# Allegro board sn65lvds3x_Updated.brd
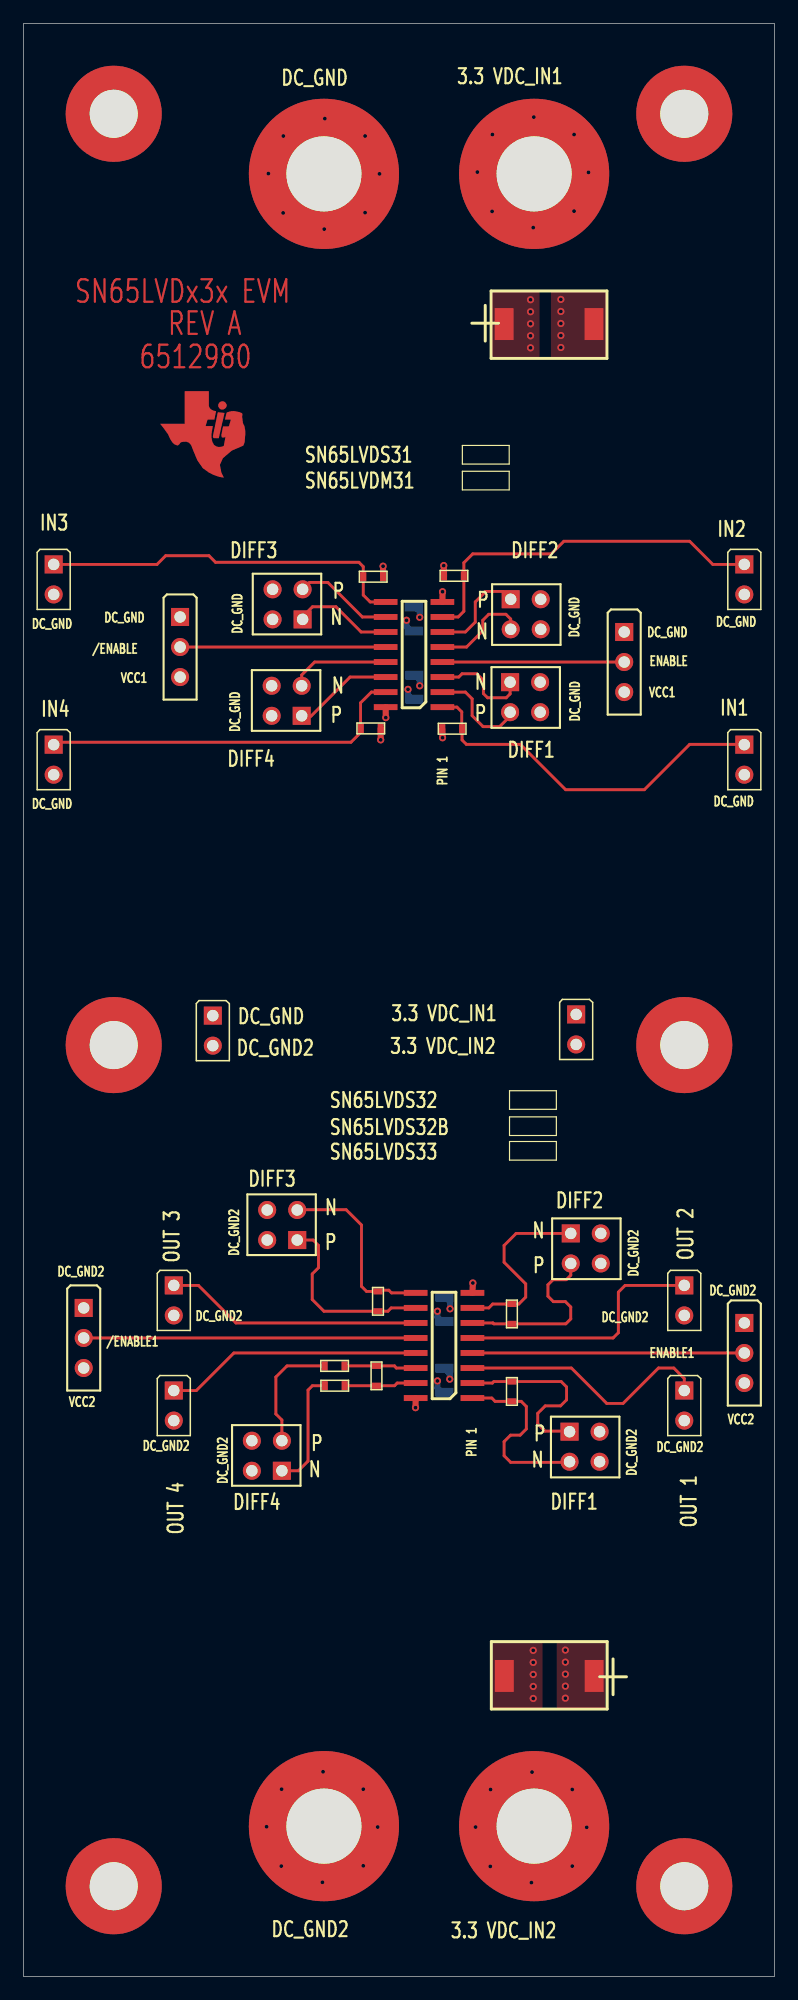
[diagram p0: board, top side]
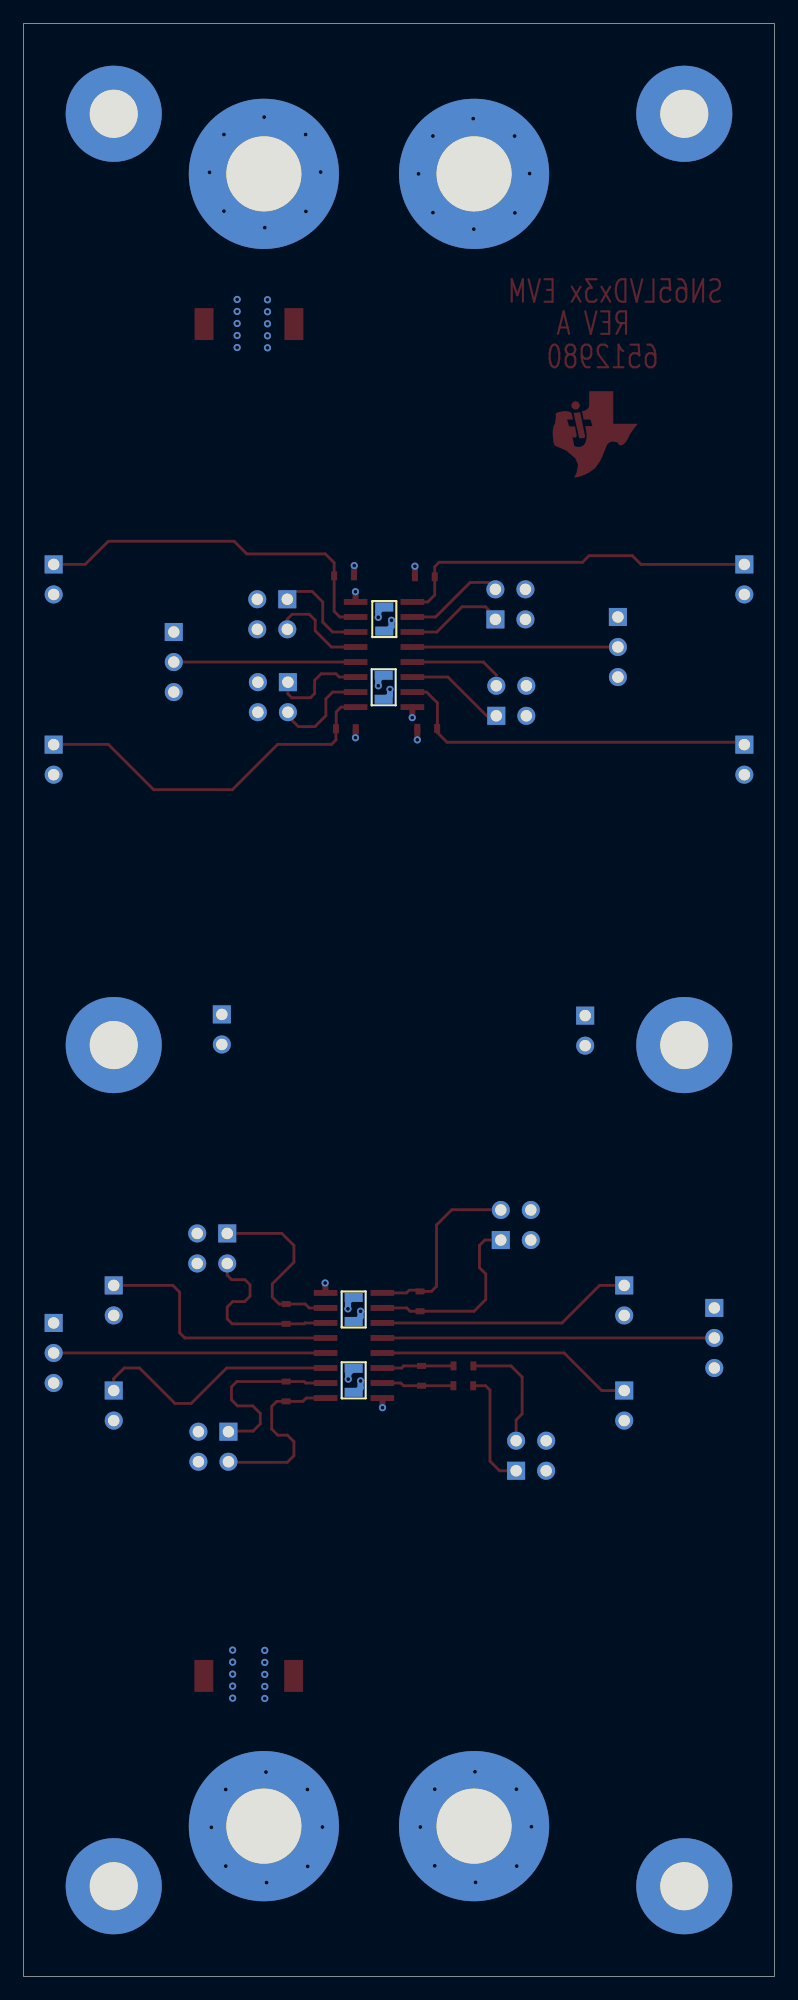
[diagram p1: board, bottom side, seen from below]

Outline 63.5 x 165.1 mm; copper layers: TOP, L2_GND, L3_VCC, BOTTOM. Coordinates in mm from the lower left corner of the outline.
Outline path: 0,165.1 0,0 63.5,0 63.5,165.1 0,165.1

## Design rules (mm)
constraint set DEFAULT: min track width 0.241

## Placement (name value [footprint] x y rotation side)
C1  10uf  [CC7343]  40.64 139.7 0 top
C2  10uf  [CC7343]  48.26 25.4 180 top
C3  .01uf  [CC0805]  33.05 107.98 90 bottom
C4  .01uf  [CC0805]  32.99 113.74 90 bottom
C5  .01uf  [CC0805]  35.59 57.4 270 bottom
C6  .01uf  [CC0805]  35.59 51.41 270 bottom
J1  HEADER 3X1  [BERG1X3]  50.8 113.66 0 top
J2  HEADER 3X1  [BERG1X3]  13.23 114.93 0 top
J3  HEADER 3X1  [BERG1X3]  60.96 55.25 0 top
J4  HEADER 3X1  [BERG1X3]  5.08 56.52 0 top
J5  Header 2x1  [BERG2]  46.74 81.33 0 top
J6  Header 2x1  [BERG2]  16 81.23 0 top
NOREF  -  []  0 165.1 0 top
NOREF#2  -  [unnamed#2]  55.88 157.48 0 top
NOREF#3  -  []  15.24 131.06 0 top
NOREF#4  -  [unnamed#2]  55.88 7.62 0 top
NOREF#5  -  [unnamed#2]  7.62 7.62 0 top
NOREF#6  -  []  -33.02 -70.94 0 top
NOREF#7  -  []  63.5 0 90 top
NOREF#8  -  [unnamed#2]  7.62 157.48 0 top
NOREF#9  -  [unnamed#2]  7.62 78.74 0 top
NOREF#10  -  [unnamed#2]  55.88 78.74 0 top
P1  Header 2x1  [BERG2]  60.96 104.14 0 top
P2  Header 2x1  [BERG2]  60.96 119.38 0 top
P3  Header 2x1  [BERG2]  2.54 119.38 0 top
P4  Header 2x1  [BERG2]  2.54 104.14 0 top
P5  Header 2x2  [BERG2X2]  41.15 109.42 0 top
P6  Header 2x2  [BERG2X2]  46.18 46.05 0 top
P7  Header 2x2  [BERG2X2]  41.2 116.43 0 top
P8  Header 2x2  [BERG2X2]  46.28 62.81 0 top
P9  Header 2x2  [BERG2X2]  23.6 114.73 180 top
P10  Header 2x2  [BERG2X2]  23.14 62.26 180 top
P11  Header 2x2  [BERG2X2]  23.52 106.58 180 top
P12  Header 2x2  [BERG2X2]  21.84 42.75 180 top
P13  Header 2x1  [BERG2]  55.88 49.53 0 top
P14  Header 2x1  [BERG2]  55.88 58.42 0 top
P15  Header 2x1  [BERG2]  12.7 58.42 0 top
P16  Header 2x1  [BERG2]  12.7 49.53 0 top
P17  VCC1_3.3V  [BJACK]  43.18 152.4 0 top
P18  GND  [BJACK]  25.4 152.4 0 top
P19  VCC2_3.3V  [BJACK]  43.18 12.7 0 top
P20  GND1  [BJACK]  25.4 12.7 0 top
R1  49.9  [R0603]  37.08 105.49 180 top
R2  49.9  [R0603]  37.24 118.41 180 top
R3  49.9  [R0603]  28.73 118.34 0 top
R4  49.9  [R0603]  28.52 105.51 0 top
R5  100  [R0603]  41.3 48.62 90 top
R6  100  [R0603]  41.3 55.17 90 top
R7  100  [R0603]  29.97 56.24 90 top
R8  0  [R0603]  25.46 51.61 0 top
R9  0  [R0603]  27.15 49.94 180 top
R10  100  [R0603]  29.85 49.94 90 top
U1  LINE DRIVER  [D16]  33.02 111.76 180 top
U2  LINE RECIEVER  [D16]  35.56 53.34 180 top

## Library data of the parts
C1 C2 = PCap7343_10uf
C3-C6 = NPCap0805_0.01uf
J1-J4 = Header 3x1
J5 J6 P1-P4 P13-P16 = Header 2x1
P5-P12 = Header 2x2_0: User Part Number: D*
P17-P20 = Banana-Jack: User Part Number: 3267
R1-R10 = r0603
U1 = 16 PIN DEVICE_1
U2 = 16 PIN DEVICE_2

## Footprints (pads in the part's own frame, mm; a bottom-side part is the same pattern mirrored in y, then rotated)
BERG1X3
  rect 1.524x1.524 hole 0.965: 1(0,0)
  round 1.524 hole 0.965: 2(0,-2.54) 3(0,-5.08)
BERG2
  rect 1.524x1.524 hole 0.965: 1(0,0)
  round 1.524 hole 0.965: 2(0,-2.54)
BERG2X2
  rect 1.524x1.524 hole 0.965: 1(0,0)
  round 1.524 hole 0.965: 2(2.54,0) 3(0,-2.54) 4(2.54,-2.54)
BJACK
  round 12.7 hole 6.35: 1(0,0)
CC0805
  rect 0.762x1.524 smd: 1(0,0) 2(2.032,0)
CC7343
  rect 1.6x2.7 smd: 1(0,0) 2(7.6,0)
D16
  rect 1.999x0.5 smd: 1(-2.4,4.445) 2(-2.4,3.175) 3(-2.4,1.905) 4(-2.4,0.635) 5(-2.4,-0.635) 6(-2.4,-1.905) 7(-2.4,-3.175) 8(-2.4,-4.445) 9(2.4,-4.445) 10(2.4,-3.175) 11(2.4,-1.905) 12(2.4,-0.635) 13(2.4,0.635) 14(2.4,1.905) 15(2.4,3.175) 16(2.4,4.445)
R0603
  rect 0.508x0.762 smd: 1(0,0) 2(1.676,0)
unnamed#2
  round 8.128 hole 4.064: (0,0)

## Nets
GND_POWER: C1.2 C3.2 C4.2 J1.1 J2.1 J6.1 P1.2 P2.2 P3.2 P4.2 P5.2 P5.4 P7.2 P7.4 P9.2 P9.4 P11.2 P11.4 P18.1(V) R1.2 R2.2 R3.2 R4.2 U1.8
GND_SIGNAL: C2.2 C5.2 C6.2 J3.1 J4.1 J6.2 P6.2 P6.4 P8.2 P8.4 P10.2 P10.4 P12.2 P12.4 P13.2 P14.2 P15.2 P16.2 P20.1(V) U2.8
VCC1: C1.1 C3.1 C4.1 J1.3 J2.3 J5.1 P17.1(V) U1.16(VCC)
VCC2: C2.1 C5.1 C6.1 J3.3 J4.3 J5.2 P19.1(V) U2.16(VCC)
/ENABLE: J2.2 U1.12
/ENABLE1: J4.2 U2.12
DIFF1_N: P5.1 U1.3
DIFF1_P: P5.3 U1.2
DIFF2_N: P7.3 U1.5
DIFF2_P: P7.1 U1.6
DIFF3_N: P9.1 U1.11
DIFF3_P: P9.3 U1.10
DIFF4_N: P11.3 U1.13
DIFF4_P: P11.1 U1.14
DIFF10_N: P6.3 R5.1 U2.1
DIFF10_P: P6.1 R5.2 U2.2
DIFF20_N: P8.1 R6.2 U2.7
DIFF20_P: P8.3 R6.1 U2.6
DIFF30_N: P10.3 R7.2 U2.9
DIFF30_P: P10.1 R7.1 U2.10
DIFF40_N: R9.1 R10.1 U2.15
DIFF40_P: R8.2 R10.2 U2.14
ENABLE: J1.2 U1.4
ENABLE1: J3.2 U2.4
IN1: P1.1 R1.1 U1.1
IN2: P2.1 R2.1 U1.7
IN3: P3.1 R3.1 U1.9
IN4: P4.1 R4.1 U1.15
OUT1: P13.1 U2.3
OUT2: P14.1 U2.5
OUT3: P15.1 U2.11
OUT4: P16.1 U2.13
N179608: P12.3 R8.1
N180034: P12.1 R9.2

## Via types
v1: diameter 0.61, hole 0.33, TOP to BOTTOM, 68 vias

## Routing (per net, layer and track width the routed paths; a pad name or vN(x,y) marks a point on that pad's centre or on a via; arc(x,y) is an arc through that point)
GND_POWER: length 58.3
  TOP w0.508: R1.2 v1(35.43,104.72) ; R4.2 v1(30.2,104.55) ; R3.2 v1(30.4,119.23) ; R2.2 v1(35.53,119.28) ; U1.8 v1(35.43,117.07)
  L2_GND w0.241: 43.74,113.02 P7.4 ; P7.4 44.62,113.89 ; P7.4 43.74,114.77 ; P7.4 42.86,113.89 ; J1.1 50.8,114.54 ; J1.1 51.68,113.66 ; J1.1 50.8,112.79 ; J1.1 49.92,113.66 ; 20.1,109.12 20.98,109.12 ; 20.98,109.12 21.86,109.12 ; 20.98,109.12 20.98,108.24 ; 20.98,109.12 20.98,109.99 ; P9.4 21.93,117.27 ; P9.4 20.18,117.27 ; P9.4 21.06,116.4 ; P9.4 21.06,118.15 ; P2.2 60.96,117.72 ; P2.2 60.96,115.96 ; P2.2 60.08,116.84 ; P2.2 61.84,116.84 ; 13.23,114.06 J2.1 ; J2.1 14.11,114.93 ; J2.1 13.23,115.81 ; J2.1 12.36,114.93 ; P4.2 3.42,101.6 ; P4.2 2.54,102.48 ; P4.2 2.54,100.72 ; P4.2 1.66,101.6 ; P1.2 61.84,101.6 ; P1.2 60.96,100.72 ; P1.2 60.08,101.6 ; P1.2 60.96,102.48 ; P5.4 43.69,107.76 ; P5.4 44.56,106.88 ; P5.4 43.69,106.01 ; P5.4 42.81,106.88 ; 21.06,113.86 P9.2 ; P9.2 20.18,114.73 ; P9.2 21.93,114.73 ; P9.2 21.06,115.61 ; 42.86,116.43 P7.2 ; P7.2 44.62,116.43 ; P7.2 43.74,115.56 ; P7.2 43.74,117.31 ; P11.2 20.98,107.45 ; P11.2 20.98,105.7 ; P11.2 21.86,106.58 ; P11.2 20.1,106.58 ; P3.2 2.54,117.72 ; P3.2 3.42,116.84 ; P3.2 1.66,116.84 ; P3.2 2.54,115.96 ; 42.81,109.42 P5.2 ; P5.2 43.69,108.55 ; P5.2 43.69,110.3 ; P5.2 44.56,109.42
  L2_GND w0.622: J6.1 16,82.11 ; J6.1 15.13,81.23 ; J6.1 16.88,81.23
  BOTTOM w0.508: v1(33.5,114.91) 33.5,115.4 33.13,115.77 C4.2 ; v1(33.5,109.12) 33.5,109.64 33.13,110.01 C3.2
  vias: v1(20.7,152.43) v1(21.95,149.1) v1(21.97,155.6) v1(25.43,147.73) v1(25.48,157.07) v1(28.88,155.6) v1(28.88,149.12) v1(30.1,152.4) v1(45.44,141.78) v1(45.44,140.77) v1(45.44,139.75) v1(45.44,138.73) v1(45.44,137.72)
GND_SIGNAL: length 55.1
  TOP w0.508: U2.8 v1(38,58.62)
  L2_GND w0.241: 12.7,55 P15.2 ; P15.2 13.58,55.88 ; P15.2 12.7,56.76 ; P15.2 11.82,55.88 ; 48.72,45.17 P6.2 ; P6.2 48.72,46.93 ; P6.2 47.84,46.05 ; P6.2 49.59,46.05 ; 55.88,46.11 P13.2 ; P13.2 55,46.99 ; P13.2 56.76,46.99 ; P13.2 55.88,47.87 ; P14.2 56.76,55.88 ; P14.2 55.88,56.76 ; P14.2 55.88,55 ; P14.2 55,55.88 ; 47.94,60.27 P8.4 ; P8.4 49.7,60.27 ; P8.4 48.82,61.15 ; P8.4 48.82,59.4 ; P16.2 13.58,46.99 ; P16.2 12.7,47.87 ; P16.2 12.7,46.11 ; P16.2 11.82,46.99 ; J3.1 61.84,55.25 ; J3.1 60.08,55.25 ; J3.1 60.96,54.37 ; J3.1 60.96,56.12 ; P6.4 49.59,43.51 ; P6.4 48.72,44.39 ; P6.4 47.84,43.51 ; P6.4 48.72,42.63 ; P8.2 49.7,62.81 ; P8.2 48.82,61.94 ; P8.2 48.82,63.69 ; P8.2 47.94,62.81 ; P10.4 21.48,64.8 ; P10.4 20.6,63.92 ; P10.4 19.72,64.8 ; P10.4 20.6,65.67 ; P12.2 19.3,43.62 ; P12.2 19.3,41.87 ; P12.2 20.18,42.75 ; P12.2 18.43,42.75 ; 18.43,45.29 P12.4 ; P12.4 20.18,45.29 ; P12.4 19.3,46.16 ; P12.4 19.3,44.41 ; 19.72,62.26 P10.2 ; P10.2 20.6,61.38 ; P10.2 21.48,62.26 ; P10.2 20.6,63.13 ; J4.1 5.96,56.52 ; J4.1 5.08,55.64 ; J4.1 4.2,56.52 ; J4.1 5.08,57.39
  L2_GND w0.622: 16,77.81 J6.2 ; J6.2 16.88,78.69 ; J6.2 15.13,78.69
  BOTTOM w0.508: C5.2 35.37,55.37 35,55.74 v1(35,56.24) ; v1(35,50.34) 35,49.75 35.37,49.38 C6.2
  vias: v1(20.55,12.65) v1(21.82,15.82) v1(21.79,9.32) v1(25.32,17.3) v1(25.27,7.95) v1(28.73,15.82) v1(28.73,9.35) v1(29.95,12.62) v1(43.1,27.56) v1(43.1,26.54) v1(43.1,25.53) v1(43.1,24.51) v1(43.1,23.5)
VCC1: length 13
  TOP w0.508: U1.16 v1(30.63,106.43)
  L3_VCC w0.241: 12.36,109.85 J2.3 ; J2.3 13.23,110.73 ; J2.3 13.23,108.98 ; J2.3 14.11,109.85 ; 50.8,107.71 J1.3 ; J1.3 50.8,109.46 ; J1.3 51.68,108.58 ; J1.3 49.92,108.58
  L3_VCC w0.622: 45.86,81.33 J5.1 ; J5.1 46.74,82.21 ; J5.1 47.61,81.33
  BOTTOM w0.508: v1(32.38,114.66) 32.38,114.11 32.75,113.74 C4.1 ; v1(32.51,108.81) 32.51,108.34 32.88,107.98 C3.1
  vias: v1(38.38,152.55) v1(39.65,155.73) v1(39.62,149.22) v1(42.88,141.76) v1(42.88,140.74) v1(42.88,139.73) v1(42.88,138.71) v1(42.88,137.69) v1(43.15,157.2) v1(43.1,147.85) v1(46.56,155.73) v1(46.56,149.25) v1(47.78,152.53)
VCC2: length 12.8
  TOP w0.508: U2.16 v1(33.15,48.08)
  L3_VCC w0.241: J4.3 5.96,51.44 ; J4.3 4.2,51.44 ; J4.3 5.08,50.56 ; J4.3 5.08,52.31 ; 60.96,49.29 J3.3 ; J3.3 60.08,50.16 ; J3.3 61.84,50.16 ; J3.3 60.96,51.04
  L3_VCC w0.622: J5.2 47.61,78.79 ; J5.2 45.86,78.79 ; J5.2 46.74,77.91
  BOTTOM w0.508: v1(36.07,56.44) 36.07,57.04 35.7,57.4 C5.1 ; v1(36.04,50.5) 36.04,50.95 C6.1
  vias: v1(38.23,12.62) v1(39.5,15.8) v1(39.47,9.3) v1(42.95,7.92) v1(43,17.27) v1(45.82,27.58) v1(45.82,26.57) v1(45.82,25.55) v1(45.82,24.54) v1(45.82,23.52) v1(46.41,15.8) v1(46.41,9.32) v1(47.62,12.6)
/ENABLE: length 17.4
  TOP w0.241: J2.2 U1.12
/ENABLE1: length 28.1
  TOP w0.241: J4.2 U2.12
DIFF1_N: length 8.5
  TOP w0.241: U1.3 36.8,109.85 37.08,110.13 38.33,110.13 38.89,109.58 38.89,108.46 39.24,108.1 40.82,108.1 41.15,108.43 P5.1
DIFF1_P: length 8.5
  TOP w0.241: U1.2 37.36,108.58 37.93,108.01 37.93,106.59 38.86,105.66 40.26,105.66 41.15,106.55 P5.3
DIFF2_N: length 8.5
  TOP w0.241: U1.5 37.46,112.39 38.84,113.77 38.84,114.66 39.34,115.16 40.79,115.16 41.2,114.76 P7.3
DIFF2_P: length 8.5
  TOP w0.241: U1.6 37.36,113.66 38.2,114.5 38.2,116.2 39.09,117.09 40.54,117.09 P7.1
DIFF3_N: length 8.5
  TOP w0.241: U1.11 28.55,113.66 26.42,115.8 24.43,115.8 23.6,114.96 P9.1
DIFF3_P: length 8.5
  TOP w0.241: P9.3 24.18,117.86 25.73,117.86 28.65,114.93 U1.10
DIFF4_N: length 8.5
  TOP w0.241: 23.52,109.12 23.52,110.03 24.61,111.12 U1.13
DIFF4_P: length 8.5
  TOP w0.241: P11.1 23.55,106.55 24.31,106.55 27.61,109.85 U1.14
DIFF10_N: length 16.1
  TOP w0.241: P6.3 46.13,43.46 41.2,43.46 40.64,44.02 40.64,45.21 41.19,45.76 42,45.76 42.52,46.28 42.52,48.18 42.09,48.62 R5.1 39.88,48.62 39.6,48.9 U2.1
DIFF10_P: length 16.1
  TOP w0.241: U2.2 39.65,50.16 39.78,50.29 R5.2 45.47,50.29 45.92,49.83 45.92,48.74 45.42,48.23 44.12,48.23 43.48,47.6 43.48,46.71 44.09,46.1 46.13,46.1 P6.1
DIFF20_N: length 16.1
  TOP w0.241: P8.1 41.66,62.81 40.64,61.8 40.64,60.38 42.47,58.55 42.47,57.43 41.88,56.85 R6.2 39.67,56.85 39.34,56.52 U2.7
DIFF20_P: length 16.1
  TOP w0.241: P8.3 46.28,59.28 45.9,58.9 44.78,58.9 44.35,58.47 44.35,57.51 44.81,57.05 45.82,57.05 46.28,56.59 46.28,55.59 45.86,55.17 R6.1 39.78,55.17 39.7,55.25 U2.6
DIFF30_N: length 16.1
  TOP w0.241: P10.3 23.16,64.82 27.28,64.82 28.57,63.53 28.57,58.34 29.01,57.91 R7.2 30.07,58.01 30.89,58.01 31.12,57.79 U2.9
DIFF30_P: length 16.1
  TOP w0.241: U2.10 31.09,56.52 30.81,56.24 R7.1 25.4,56.24 24.41,57.23 24.41,59.39 24.94,59.92 24.94,61.8 24.49,62.26 P10.1
DIFF40_N: length 6.1
  TOP w0.241: U2.15 31.6,50.16 31.37,49.94 R10.1 R9.1
DIFF40_P: length 6.1
  TOP w0.241: R8.2 R10.2 31.37,51.61 31.52,51.44 U2.14
ENABLE: length 15.4
  TOP w0.241: J1.2 U1.4
ENABLE1: length 23
  TOP w0.241: J3.2 U2.4
IN1: length 31.4
  TOP w0.241: U1.1 36.65,107.31 37.06,106.91 37.06,105.51 R1.1 37.08,104.53 37.45,104.17 42.01,104.17 45.85,100.33 52.5,100.33 56.34,104.17 60.93,104.17 P1.1
IN2: length 31.4
  TOP w0.241: U1.7 36.75,114.93 37.24,115.42 R2.1 37.24,119.52 37.99,120.27 44.63,120.27 45.69,121.34 56.34,121.34 58.29,119.38 P2.1
IN3: length 31.4
  TOP w0.241: U1.9 29.31,116.2 28.73,116.79 R3.1 28.73,119.19 28.36,119.56 16.23,119.56 15.67,120.12 12.01,120.12 11.28,119.38 P3.1
IN4: length 31.4
  TOP w0.241: U1.15 29.41,108.58 28.5,107.67 28.5,105.54 R4.1 28.52,105.18 27.69,104.34 2.74,104.34 P4.1
OUT1: length 21.8
  TOP w0.241: P13.1 55.88,50.55 54.99,51.44 53.7,51.44 50.7,48.44 49.33,48.44 46.33,51.44 U2.3
OUT2: length 21.8
  TOP w0.241: P14.1 50.88,58.42 50.3,57.85 50.3,54.42 49.86,53.98 U2.5
OUT3: length 21.8
  TOP w0.241: P15.1 14.78,58.42 17.96,55.25 U2.11
OUT4: length 21.8
  TOP w0.241: U2.13 17.78,52.71 14.61,49.53 P16.1
N179608: length 10.1
  TOP w0.241: P12.3 21.84,47.04 21.34,47.55 21.34,50.67 22.28,51.61 R8.1
N180034: length 10.1
  TOP w0.241: R9.2 24.42,49.94 24.05,49.57 24.05,43.56 23.24,42.75 P12.1

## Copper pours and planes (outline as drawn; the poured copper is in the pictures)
GND_POWER on TOP: 49.35,142.49 49.35,136.78 44.6,136.78 44.6,142.49
GND_POWER on L2_GND: 0.63,164.47 0.63,80.54 62.86,80.54 62.86,164.47
GND_SIGNAL on TOP: 39.57,28.27 39.57,22.61 43.89,22.61 43.89,28.27
GND_SIGNAL on L2_GND: 0.63,1.27 0.63,79.5 62.86,79.5 62.86,1.27
VCC1 on TOP: 39.6,142.49 39.6,136.88 43.64,136.88 43.64,142.49
VCC1 on L3_VCC: 0.63,164.47 0.63,80.52 62.86,80.52 62.86,164.47
VCC2 on TOP: 49.35,28.3 49.35,22.61 45.09,22.61 45.09,28.3
VCC2 on L3_VCC: 0.63,1.27 0.63,79.53 62.86,79.53 62.86,1.27
Net_1 on TOP (solid shape): 15.66,132.78 15.74,132.6 15.86,132.48 16.07,132.37 16.28,132.34 16.13,131.63 15.55,131.63 15.39,131.07 16,131.07 15.89,130.39 15.89,130.1 15.97,129.72 16.1,129.48 16.34,129.34 16.49,129.31 16.71,129.32 16.75,129.33 16.93,129.39 17.08,130.19 16.99,130.12 16.87,130.1 16.76,130.13 16.72,130.3 16.87,131.05 17.36,131.05 17.53,131.63 17.03,131.63 17.17,132.21 17.4,132.3 17.6,132.34 17.82,132.34 18.23,132.26 18.45,132.18 18.5,132.1 18.48,131.87 18.55,131.35 18.59,131.24 18.67,131.09 18.74,130.73 18.75,130.4 18.68,129.68 18.58,129.42 17.61,129.01 16.85,128.36 16.6,127.8 16.73,127.15 16.93,126.72 16.58,126.77 16.31,126.86 16.05,126.95 15.67,127.15 15.16,127.52 14.7,128.17 14.37,128.95 14.16,129.48 13.98,129.67 13.77,129.76 13.5,129.75 13.33,129.71 13.26,129.67 13.17,129.55 13.05,129.44 12.94,129.45 12.74,129.54 12.6,129.66 12.4,129.97 12.21,130.39 11.9,130.82 11.55,131.27 11.97,131.27 13.62,131.27 13.62,134.03 15.66,134.03
Net_2 on TOP (solid shape): 16.99,132.19 16.58,130.37 16.51,130.05 16.08,130.06 16.02,130.13 16.01,130.21 16.42,132.24 16.42,132.24

Small or netless copper shapes (teardrops, artwork), in the pictures only: 1 on TOP

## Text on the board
TOP: SN65LVDx3x EVM | 6512980 | REV A
Board Geometry/Soldermask Top: SN65LVDx3x EVM | 6512980 | REV A
Ref Des/Silkscreen Top: DC_GND | DC_GND2 | VCC2 | /ENABLE | /ENABLE1 | VCC1 | ENABLE | ENABLE1 | PIN 1 | IN3 | IN4 | DIFF4 | DIFF3 | SN65LVDS31 | SN65LVDM31 | N | P | SN65LVDS32 | SN65LVDS32B | SN65LVDS33 | 3.3 VDC_IN2 | 3.3 VDC_IN1 | DIFF1 | DIFF2 | IN2 | IN1 | OUT 3 | OUT 4 | OUT 2 | OUT 1
Board Geometry/Design Outline: 45 mil | 5mil | 1 | 2 | 3 | 4 | TOP | V1 | GND7 | V2
PAGE_OUTLINE: GENERAL NOTES. UNLESS OTHERWISE SPECIFIED | 1.  ALL FABRICATION ITEMS MUST MEET OR EXCEED BEST | INDUSTRY PRACTICE : IPC-A-600C (Commercial std.) | 2.  LAMINATE MATERIAL  :  FR4 POLYCLAD 370 or EQUIVALENT | 3.  COPPER WEIGHT  : 1oz START INTERNAL, 1/2oz START EXTERNAL | 4.  FINISHED BOARD THICKNESS :  .062  +/- 10% | 5.  MAXIMUM WARP AND TWIST TO BE :  .005 INCH PER INCH | 6.  MINIMUM COPPER WALL THICKNESS OF PLATED-THRU | HOLES TO BE .001 INCH. THERE MUST BE 1MIL OR GREATER PLATING ON | EACH SIDE OF THE BARREL WHEN VIEWED IN THE CROSS SECTION | 7.  MINIMUM ANNULAR RING OF PLATED-THRU HOLES | TO BE .002 INCH | 8.  MINIMUM ALLOWABLE LINE REDUCTION TO BE | 20% OR .002 WHICHEVER IS GREATER | 10. 0.0095 SIGNAL LINES ON LAYER 1 & 4 TO BE | IMPEDENCE CONTROLLED 50 OHMS | 11. DIELECTRIC CONSTANTS ARE      CORE : 4.1 | PREPREG : 4.1 | 13. A CROSS SECTION MOUNT AND DIGITAL PHOTO'S OF VIA'S TO BE PROVIDED | 14. USE THE (DRPP) DUTCH REVERSE PLATING PROCESS | PROCESS NOTES | 1. CIRCUITRY ON OUTER LAYERS TO BE PLATED WITH : NICKEL GOLD | 2. SOLDERMASK BOTH SIDES PER ARTWORK  :  GREEN LPI | 3. SILKSCREEN BOTH SIDES PER ARTWORK  :  COLOR = WHITE | FIGURE | SIZE | 13.0 | 38.0 | 160.0 | 250.0 | DRILL CHART: TOP to BOTTOM | ALL UNITS ARE IN MILS | PLATED | QTY | 68 | 64 | 6 | 4
